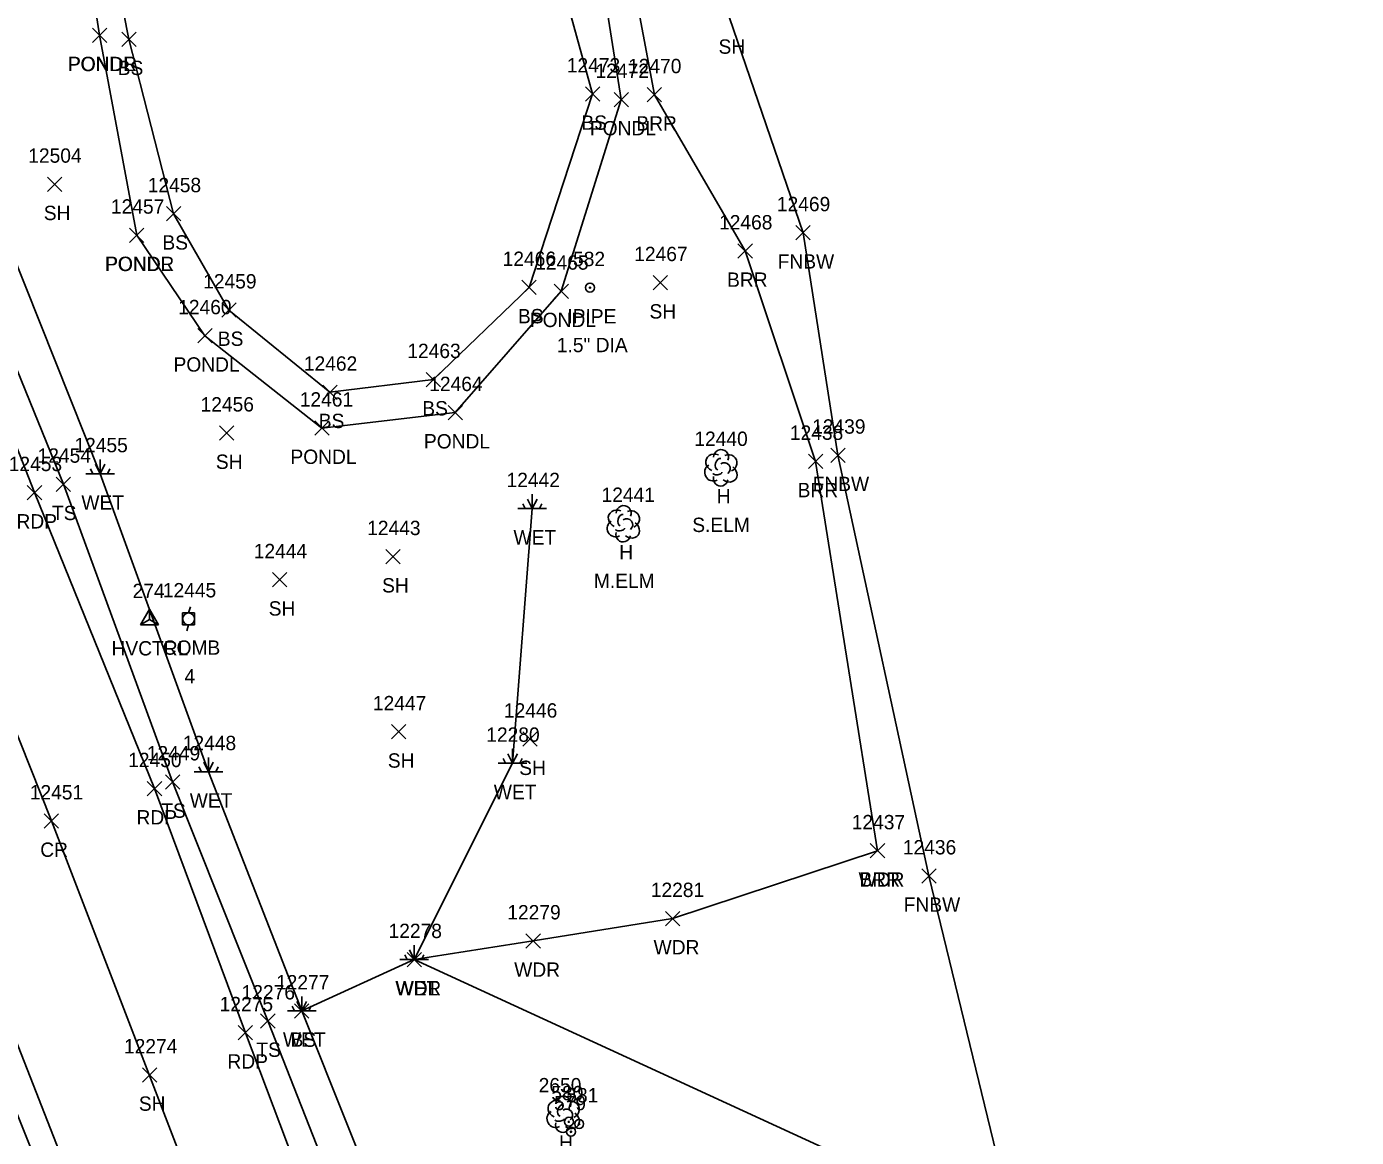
# Model space of a CAD drawing. Extents: x 1439173 to 1457902, y 641926 to 659889.
# Drawn here: x 1447721.4 to 1447906.7, y 649724.3 to 649879.1 of the extents above; entities that cross this region are included whole.
import ezdxf

# ---------------------------------------------------------------- set-up
doc = ezdxf.new("R2010")
doc.units = 0
for name, color, linetype in [('C_A', 7, 'Continuous'), ('C_I', 7, 'Continuous'), ('CPSM', 7, 'Continuous'), ('L_A', 7, 'Continuous'), ('L_C', 7, 'Continuous'), ('L_I', 7, 'Continuous'), ('L_TIC', 7, 'Continuous'), ('LABL', 7, 'Continuous'), ('LAWA', 7, 'Continuous'), ('LAWE', 7, 'Continuous'), ('LELB', 7, 'Continuous'), ('LFNC', 7, 'Continuous'), ('LSOGP', 7, 'Continuous'), ('LTD', 7, 'Continuous'), ('LWET', 7, 'Continuous'), ('M_A', 7, 'Continuous'), ('M_C', 7, 'Continuous'), ('M_I', 7, 'Continuous'), ('MPIP', 7, 'Continuous'), ('P_A', 7, 'Continuous'), ('P_I', 7, 'Continuous'), ('P_TIC', 7, 'Continuous'), ('PET', 7, 'Continuous'), ('PRC', 7, 'Continuous'), ('U_A', 7, 'Continuous'), ('U_C', 7, 'Continuous'), ('U_I', 7, 'Continuous'), ('UP', 7, 'Continuous')]:
    doc.layers.add(name, color=color, linetype=linetype)

msp = doc.modelspace()

# ---------------------------------------------------------------- linework, layer by layer
at = {"layer": 'CPSM'}
for p, q in [((1447737.3, 649795.72), (1447738.55, 649797.88)), ((1447739.8, 649795.72), (1447738.55, 649797.88)), ((1447738.55, 649796.44), (1447738.55, 649797.88)), ((1447737.3, 649795.72), (1447738.55, 649796.44)), ((1447737.3, 649795.72), (1447739.8, 649795.72)), ((1447738.55, 649796.44), (1447738.55, 649796.44)), ((1447738.55, 649796.44), (1447739.8, 649795.72))]:
    msp.add_line(p, q, dxfattribs=at)
at = {"layer": 'L_TIC'}
for points in [[(1447730.57, 649876.9), (1447732.57, 649878.9)], [(1447732.57, 649876.9), (1447730.57, 649878.9)], [(1447730.57, 649876.9), (1447732.57, 649878.9)], [(1447732.57, 649876.9), (1447730.57, 649878.9)], [(1447734.66, 649876.35), (1447736.66, 649878.35)], [(1447736.66, 649876.35), (1447734.66, 649878.35)], [(1447734.66, 649876.35), (1447736.66, 649878.35)], [(1447736.66, 649876.35), (1447734.66, 649878.35)], [(1447799.27, 649868.72), (1447801.27, 649870.72)], [(1447801.27, 649868.72), (1447799.27, 649870.72)], [(1447803.27, 649867.94), (1447805.27, 649869.94)], [(1447805.27, 649867.94), (1447803.27, 649869.94)], [(1447807.88, 649868.61), (1447809.88, 649870.61)], [(1447809.88, 649868.61), (1447807.88, 649870.61)], [(1447724.31, 649856.13), (1447726.31, 649858.13)], [(1447726.31, 649856.13), (1447724.31, 649858.13)], [(1447740.88, 649852.02), (1447742.88, 649854.02)], [(1447742.88, 649852.02), (1447740.88, 649854.02)], [(1447740.88, 649852.02), (1447742.88, 649854.02)], [(1447742.88, 649852.02), (1447740.88, 649854.02)], [(1447735.75, 649849.03), (1447737.75, 649851.03)], [(1447737.75, 649849.03), (1447735.75, 649851.03)], [(1447735.75, 649849.03), (1447737.75, 649851.03)], [(1447737.75, 649849.03), (1447735.75, 649851.03)], [(1447828.59, 649849.37), (1447830.59, 649851.37)], [(1447830.59, 649849.37), (1447828.59, 649851.37)], [(1447820.53, 649846.83), (1447822.53, 649848.83)], [(1447822.53, 649846.83), (1447820.53, 649848.83)], [(1447790.43, 649841.74), (1447792.43, 649843.74)], [(1447792.43, 649841.74), (1447790.43, 649843.74)], [(1447794.91, 649841.22), (1447796.91, 649843.22)], [(1447796.91, 649841.22), (1447794.91, 649843.22)], [(1447808.71, 649842.41), (1447810.71, 649844.41)], [(1447810.71, 649842.41), (1447808.71, 649844.41)], [(1447748.61, 649838.6), (1447750.61, 649840.6)], [(1447750.61, 649838.6), (1447748.61, 649840.6)], [(1447745.26, 649835.01), (1447747.26, 649837.01)], [(1447747.26, 649835.01), (1447745.26, 649837.01)], [(1447777.1, 649828.9), (1447779.1, 649830.9)], [(1447779.1, 649828.9), (1447777.1, 649830.9)], [(1447762.68, 649827.14), (1447764.68, 649829.14)], [(1447764.68, 649827.14), (1447762.68, 649829.14)], [(1447780.14, 649824.3), (1447782.14, 649826.3)], [(1447782.14, 649824.3), (1447780.14, 649826.3)], [(1447748.29, 649821.45), (1447750.29, 649823.45)], [(1447750.29, 649821.45), (1447748.29, 649823.45)], [(1447761.55, 649822.14), (1447763.55, 649824.14)], [(1447763.55, 649822.14), (1447761.55, 649824.14)], [(1447830.35, 649817.5), (1447832.35, 649819.5)], [(1447832.35, 649817.5), (1447830.35, 649819.5)], [(1447833.46, 649818.36), (1447835.46, 649820.36)], [(1447835.46, 649818.36), (1447833.46, 649820.36)], [(1447725.53, 649814.31), (1447727.53, 649816.31)], [(1447727.53, 649814.31), (1447725.53, 649816.31)], [(1447771.45, 649804.22), (1447773.45, 649806.22)], [(1447773.45, 649804.22), (1447771.45, 649806.22)], [(1447755.66, 649801), (1447757.66, 649803)], [(1447757.66, 649801), (1447755.66, 649803)], [(1447772.25, 649779.8), (1447774.25, 649781.8)], [(1447774.25, 649779.8), (1447772.25, 649781.8)], [(1447790.57, 649778.78), (1447792.57, 649780.78)], [(1447792.57, 649778.78), (1447790.57, 649780.78)], [(1447740.76, 649772.81), (1447742.76, 649774.81)], [(1447742.76, 649772.81), (1447740.76, 649774.81)], [(1447838.97, 649763.21), (1447840.97, 649765.21)], [(1447840.97, 649763.21), (1447838.97, 649765.21)], [(1447838.97, 649763.21), (1447840.97, 649765.21)], [(1447840.97, 649763.21), (1447838.97, 649765.21)], [(1447846.14, 649759.71), (1447848.14, 649761.71)], [(1447848.14, 649759.71), (1447846.14, 649761.71)], [(1447810.41, 649753.77), (1447812.41, 649755.77)], [(1447812.41, 649753.77), (1447810.41, 649755.77)], [(1447790.99, 649750.65), (1447792.99, 649752.65)], [(1447792.99, 649750.65), (1447790.99, 649752.65)], [(1447774.43, 649748.05), (1447776.43, 649750.05)], [(1447776.43, 649748.05), (1447774.43, 649750.05)], [(1447774.43, 649748.05), (1447776.43, 649750.05)], [(1447776.43, 649748.05), (1447774.43, 649750.05)], [(1447758.75, 649740.89), (1447760.75, 649742.89)], [(1447760.75, 649740.89), (1447758.75, 649742.89)], [(1447754.02, 649739.49), (1447756.02, 649741.49)], [(1447756.02, 649739.49), (1447754.02, 649741.49)], [(1447737.57, 649731.97), (1447739.57, 649733.97)], [(1447739.57, 649731.97), (1447737.57, 649733.97)]]:
    msp.add_lwpolyline(points, dxfattribs=at)
at = {"layer": 'LABL'}
msp.add_lwpolyline([(1447839.97, 649764.21), (1447831.35, 649818.5), (1447821.53, 649847.83), (1447808.88, 649869.61), (1447802.58, 649903.3), (1447787, 649920.26), (1447770.77, 649944.53), (1447761.79, 649968.82), (1447755.13, 650001.32), (1447731.91, 649996.86), (1447719.7, 649996.24)], dxfattribs=at)
at = {"layer": 'LAWA'}
for points in [[(1447775.43, 649749.05), (1447791.99, 649751.65), (1447811.41, 649754.77), (1447839.97, 649764.21)], [(1447775.43, 649749.05), (1447846.21, 649716.48)]]:
    msp.add_lwpolyline(points, dxfattribs=at)
at = {"layer": 'LAWE'}
for points in [[(1447736.75, 649850.03), (1447746.26, 649836.01), (1447762.55, 649823.14), (1447781.14, 649825.3), (1447795.91, 649842.22), (1447804.27, 649868.94), (1447798.96, 649902.6), (1447784.97, 649913.87), (1447757.99, 649915.79), (1447736.66, 649904.86), (1447728.59, 649897.4), (1447731.57, 649877.9)], [(1447736.75, 649850.03), (1447731.57, 649877.9)]]:
    msp.add_lwpolyline(points, dxfattribs=at)
at = {"layer": 'LELB'}
for points in [[(1447774.29, 649691.46), (1447755.02, 649740.49), (1447741.76, 649773.81), (1447726.53, 649815.31), (1447711.79, 649851.58), (1447694.8, 649894.93), (1447679.35, 649935.48), (1447671.24, 649953.99), (1447664.82, 649972.77), (1447658.14, 649990.48), (1447642.81, 650028.26), (1447624.72, 650071.67), (1447610.83, 650104.7), (1447593.41, 650149.12), (1447575.75, 650192.36), (1447557, 650239.72), (1447541.41, 650280.13), (1447523.46, 650325.06), (1447503.16, 650377.6)], [(1447723.82, 649718.23), (1447707.42, 649759.24), (1447691.24, 649802.92), (1447677.6, 649836.74), (1447660.97, 649879.47), (1447648.74, 649908.2), (1447635.58, 649941.11), (1447623.44, 649965.2), (1447610.18, 649980.39), (1447590.88, 649987.45), (1447563.69, 649981.71), (1447542.89, 649971.32), (1447515.03, 649972), (1447498.96, 649966.2), (1447485.41, 649965.68), (1447480.38, 649958.04), (1447479.78, 649949.45)], [(1447741.88, 649853.02), (1447749.61, 649839.6), (1447763.68, 649828.14), (1447778.1, 649829.9), (1447791.43, 649842.74), (1447800.27, 649869.72), (1447793.36, 649894.88), (1447781.05, 649907.1), (1447758.48, 649907.27), (1447740.49, 649898.87), (1447732.63, 649892.69), (1447735.66, 649877.35)], [(1447741.88, 649853.02), (1447735.66, 649877.35)], [(1447880.13, 649239.76), (1447875.85, 649278.11), (1447869.91, 649316.47), (1447864.43, 649354.84), (1447857.47, 649403.89), (1447849.64, 649447.67), (1447838.99, 649494.14), (1447825.85, 649553.36), (1447811.08, 649599.11), (1447797.18, 649651.08), (1447779.23, 649693.18), (1447759.75, 649741.89)]]:
    msp.add_lwpolyline(points, dxfattribs=at)
at = {"layer": 'LFNC'}
msp.add_lwpolyline([(1447906.7, 649498.5), (1447900.26, 649522.32), (1447891.02, 649568.93), (1447878.05, 649621.9), (1447866.97, 649668.6), (1447857.32, 649718.69), (1447847.14, 649760.71), (1447834.46, 649819.36), (1447829.59, 649850.37)], dxfattribs=at)
at = {"layer": 'LSOGP'}
msp.add_lwpolyline([(1447619.03, 650360.07), (1447637.42, 650315.88), (1447658.67, 650267.12), (1447673.57, 650226.26), (1447688.13, 650176.69), (1447711.15, 650147.55), (1447725.49, 650099.49), (1447742.44, 650053.11), (1447746.12, 650031.62), (1447770.15, 650000.07), (1447776.52, 649966.69), (1447797.12, 649942.22), (1447810.31, 649916.5), (1447819.33, 649880.31), (1447829.59, 649850.37), (1447834.46, 649819.36), (1447847.14, 649760.71), (1447857.32, 649718.69)], dxfattribs=at)
at = {"layer": 'LTD'}
for p, q in [((1447818.13, 649817.65), (1447818.13, 649817.65)), ((1447818.13, 649817.65), (1447818.13, 649817.65)), ((1447804.54, 649809.85), (1447804.54, 649809.85)), ((1447804.54, 649809.85), (1447804.54, 649809.85)), ((1447796.15, 649727.54), (1447796.15, 649727.54)), ((1447796.15, 649727.54), (1447796.15, 649727.54))]:
    msp.add_line(p, q, dxfattribs=at)
for centre in [(1447818.17, 649819.09), (1447804.59, 649811.28), (1447796.2, 649728.97)]:
    msp.add_arc(centre, 1.05, 335.5272, 180.9563, dxfattribs=at)
for centre, major_axis, ratio, start_param, end_param in [((1447817.34, 649818.32), (1.21, -0.51), 0.895232, 1.570796, 4.712389), ((1447817.92, 649818.11), (-0.208, -0.792), 0.645439, 3.141593, 6.283185), ((1447819.17, 649818.24), (-1.14, -0.48), 0.949671, 1.570796, 4.712389), ((1447817.04, 649816.94), (0.58, -1.04), 0.959034, 3.141593, 6.283185), ((1447817.67, 649816.9), (-0.625, -0.083), 0.423636, 0, 3.141593), ((1447818.63, 649817.49), (-0.5, 0.667), 0.989748, 3.141593, 6.283185), ((1447819.13, 649816.82), (-1.09, 0.79), 0.841452, 1.570796, 4.712389), ((1447818.13, 649816.15), (0.26, 1.06), 0.942809, 1.570796, 4.712389), ((1447803.75, 649810.52), (1.21, -0.51), 0.895232, 1.570796, 4.712389), ((1447805.58, 649810.43), (-1.14, -0.48), 0.949671, 1.570796, 4.712389), ((1447803.46, 649809.14), (0.58, -1.04), 0.959034, 3.141593, 6.283185), ((1447804.34, 649810.31), (-0.208, -0.792), 0.645439, 3.141593, 6.283185), ((1447805.04, 649809.68), (-0.5, 0.667), 0.989748, 3.141593, 6.283185), ((1447805.54, 649809.02), (-1.09, 0.79), 0.841452, 1.570796, 4.712389), ((1447804.54, 649808.35), (0.26, 1.06), 0.942809, 1.570796, 4.712389), ((1447804.09, 649809.1), (-0.625, -0.083), 0.423636, 0, 3.141593), ((1447795.36, 649728.21), (1.21, -0.51), 0.895232, 1.570796, 4.712389), ((1447795.95, 649728), (-0.208, -0.792), 0.645439, 3.141593, 6.283185), ((1447796.65, 649727.37), (-0.5, 0.667), 0.989748, 3.141593, 6.283185), ((1447797.2, 649728.12), (-1.14, -0.48), 0.949671, 1.570796, 4.712389), ((1447795.07, 649726.83), (0.58, -1.04), 0.959034, 3.141593, 6.283185), ((1447796.15, 649726.04), (0.26, 1.06), 0.942809, 1.570796, 4.712389), ((1447795.7, 649726.79), (-0.625, -0.083), 0.423636, 0, 3.141593), ((1447797.15, 649726.71), (-1.09, 0.79), 0.841452, 1.570796, 4.712389)]:
    msp.add_ellipse(centre, major_axis=major_axis, ratio=ratio, start_param=start_param, end_param=end_param, dxfattribs=at)
at = {"layer": 'LWET'}
for p, q in [((1447730.66, 649816.77), (1447730.33, 649817.44)), ((1447731.66, 649816.77), (1447730.99, 649818.11)), ((1447731.66, 649816.77), (1447731.66, 649818.77)), ((1447731.66, 649816.77), (1447732.33, 649818.11)), ((1447732.66, 649816.77), (1447732.99, 649817.44)), ((1447733.66, 649816.77), (1447729.66, 649816.77)), ((1447791.87, 649811.91), (1447791.2, 649813.24)), ((1447791.87, 649811.91), (1447791.87, 649813.91)), ((1447791.87, 649811.91), (1447792.54, 649813.24)), ((1447793.87, 649811.91), (1447789.87, 649811.91)), ((1447790.87, 649811.91), (1447790.54, 649812.57)), ((1447792.87, 649811.91), (1447793.2, 649812.57)), ((1447789.13, 649776.41), (1447789.13, 649778.41)), ((1447746.76, 649775.24), (1447746.09, 649776.57)), ((1447746.76, 649775.24), (1447746.76, 649777.24)), ((1447746.76, 649775.24), (1447747.42, 649776.57)), ((1447791.13, 649776.41), (1447787.13, 649776.41)), ((1447788.13, 649776.41), (1447787.8, 649777.08)), ((1447789.13, 649776.41), (1447788.47, 649777.75)), ((1447789.13, 649776.41), (1447789.8, 649777.75)), ((1447790.13, 649776.41), (1447790.47, 649777.08)), ((1447748.76, 649775.24), (1447744.76, 649775.24)), ((1447745.76, 649775.24), (1447745.42, 649775.9)), ((1447747.76, 649775.24), (1447748.09, 649775.9)), ((1447775.43, 649749.05), (1447774.76, 649750.39)), ((1447775.43, 649749.05), (1447775.43, 649751.05)), ((1447775.43, 649749.05), (1447776.1, 649750.39)), ((1447777.43, 649749.05), (1447773.43, 649749.05)), ((1447774.43, 649749.05), (1447774.1, 649749.72)), ((1447776.43, 649749.05), (1447776.76, 649749.72)), ((1447759.75, 649741.89), (1447759.08, 649743.22)), ((1447759.75, 649741.89), (1447759.08, 649743.22)), ((1447759.75, 649741.89), (1447759.75, 649743.89)), ((1447759.75, 649741.89), (1447759.75, 649743.89)), ((1447759.75, 649741.89), (1447760.42, 649743.22)), ((1447759.75, 649741.89), (1447760.42, 649743.22)), ((1447761.75, 649741.89), (1447757.75, 649741.89)), ((1447761.75, 649741.89), (1447757.75, 649741.89)), ((1447758.75, 649741.89), (1447758.42, 649742.56)), ((1447758.75, 649741.89), (1447758.42, 649742.56)), ((1447760.75, 649741.89), (1447761.08, 649742.56)), ((1447760.75, 649741.89), (1447761.08, 649742.56))]:
    msp.add_line(p, q, dxfattribs=at)
for points in [[(1447759.75, 649741.89), (1447746.76, 649775.24), (1447731.66, 649816.77), (1447716.96, 649853.54), (1447699.99, 649897.87), (1447692.42, 649923.04), (1447688.9, 649933.67)], [(1447759.75, 649741.89), (1447775.43, 649749.05), (1447789.13, 649776.41), (1447791.87, 649811.91)]]:
    msp.add_lwpolyline(points, dxfattribs=at)
at = {"layer": 'MPIP'}
for centre, radius in [((1447799.91, 649842.72), 0.625), ((1447799.91, 649842.72), 0.0833), ((1447796.97, 649726.44), 0.625), ((1447796.97, 649726.44), 0.0833), ((1447798.4, 649726.14), 0.625), ((1447798.4, 649726.14), 0.0833), ((1447797.27, 649725.05), 0.625), ((1447797.27, 649725.05), 0.0833)]:
    msp.add_circle(centre, radius, dxfattribs=at)
at = {"layer": 'P_TIC'}
for points in [[(1447721.51, 649813.14), (1447723.51, 649815.14)], [(1447723.51, 649813.14), (1447721.51, 649815.14)], [(1447738.23, 649771.88), (1447740.23, 649773.88)], [(1447740.23, 649771.88), (1447738.23, 649773.88)], [(1447723.87, 649767.37), (1447725.87, 649769.37)], [(1447725.87, 649767.37), (1447723.87, 649769.37)], [(1447750.9, 649737.85), (1447752.9, 649739.85)], [(1447752.9, 649737.85), (1447750.9, 649739.85)]]:
    msp.add_lwpolyline(points, dxfattribs=at)
at = {"layer": 'PET'}
for points in [[(1447770.26, 649690.21), (1447751.9, 649738.85), (1447739.23, 649772.88), (1447722.51, 649814.14), (1447708.42, 649850.04), (1447690.94, 649894.41), (1447668.44, 649951.98), (1447651.8, 649993.39), (1447639.52, 650024.92), (1447621.07, 650070.34), (1447607.4, 650104.2), (1447589.96, 650148.16), (1447572.98, 650191.37), (1447554, 650238.81), (1447538.2, 650279.02), (1447520.31, 650323.9), (1447499.97, 650376.7)], [(1447727.24, 649719.06), (1447711.09, 649760.24), (1447693.62, 649804.98), (1447680.5, 649838.27), (1447663.74, 649880.79), (1447652.33, 649909.76), (1447638.93, 649943.34), (1447628.9, 649967.78), (1447622.17, 649981.56), (1447611.58, 650013.54), (1447596.45, 650049.26), (1447579.87, 650091.8), (1447553.03, 650160.19), (1447534.14, 650208.59), (1447519.57, 650245.32), (1447501.85, 650290.55), (1447485.96, 650331.56), (1447471.86, 650366.58)]]:
    msp.add_lwpolyline(points, dxfattribs=at)
at = {"layer": 'PRC'}
msp.add_lwpolyline([(1447756.88, 649685.17), (1447724.87, 649768.37), (1447708.6, 649809.19), (1447694.68, 649845.27), (1447676.47, 649890.48), (1447654.25, 649946.92), (1447638.2, 649987.7), (1447625.62, 650020.15), (1447607.06, 650065.42), (1447594.17, 650098.1), (1447576.34, 650142.25), (1447558.92, 650186.5), (1447540.22, 650233.49), (1447524.32, 650273.63), (1447506.57, 650318.67), (1447486.08, 650370.95)], dxfattribs=at)
at = {"layer": 'UP'}
for p, q in [((1447743.15, 649795.71), (1447743.15, 649797.38)), ((1447743.15, 649797.38), (1447744.81, 649797.38)), ((1447744.23, 649798.21), (1447743.98, 649797.38)), ((1447743.98, 649796.54), (1447743.98, 649796.54)), ((1447744.81, 649797.38), (1447744.81, 649795.71)), ((1447744.81, 649795.71), (1447743.15, 649795.71)), ((1447743.73, 649794.88), (1447743.98, 649795.71))]:
    msp.add_line(p, q, dxfattribs=at)
msp.add_circle((1447743.98, 649796.54), 0.833, dxfattribs=at)

# ---------------------------------------------------------------- texts
at = {"layer": 'C_A'}
msp.add_text('HVCTRL', height=2, dxfattribs=at).set_placement((1447733.24, 649791.44))
at = {"layer": 'C_I'}
msp.add_text('274', height=2, dxfattribs=at).set_placement((1447736.18, 649799.44))
at = {"layer": 'L_A'}
for s, p in [('SH', (1447817.82, 649875.32)), ('PONDR', (1447727.13, 649872.9)), ('PONDL', (1447727.19, 649872.9)), ('BS', (1447734.1, 649872.35)), ('BS', (1447734.1, 649872.35)), ('BS', (1447798.71, 649864.72)), ('PONDL', (1447799.89, 649863.94)), ('BRR', (1447806.37, 649864.61)), ('SH', (1447723.8, 649852.13)), ('BS', (1447740.33, 649848.02)), ('BS', (1447740.33, 649848.02)), ('PONDR', (1447732.32, 649845.03)), ('PONDL', (1447732.38, 649845.03)), ('FNBW', (1447826.06, 649845.37)), ('BRR', (1447819.01, 649842.83)), ('BS', (1447789.87, 649837.74)), ('PONDL', (1447791.53, 649837.22)), ('SH', (1447808.2, 649838.41)), ('BS', (1447748.05, 649834.6)), ('PONDL', (1447741.88, 649831.01)), ('BS', (1447776.54, 649824.9)), ('BS', (1447762.12, 649823.14)), ('PONDL', (1447776.77, 649820.3)), ('SH', (1447747.78, 649817.45)), ('PONDL', (1447758.17, 649818.14)), ('BRR', (1447828.84, 649813.5)), ('FNBW', (1447830.93, 649814.36)), ('WET', (1447729.04, 649811.77)), ('H', (1447817.56, 649812.65)), ('TS', (1447724.94, 649810.31)), ('WET', (1447789.25, 649806.91)), ('H', (1447803.98, 649804.85)), ('SH', (1447770.94, 649800.22)), ('SH', (1447755.14, 649797)), ('SH', (1447771.74, 649775.8)), ('SH', (1447790.05, 649774.78)), ('WET', (1447786.51, 649771.41)), ('TS', (1447740.17, 649768.81)), ('WET', (1447744.14, 649770.24)), ('WDR', (1447837.33, 649759.21)), ('BRR', (1447837.46, 649759.21)), ('FNBW', (1447843.62, 649755.71)), ('WDR', (1447808.77, 649749.77)), ('WDR', (1447789.35, 649746.65)), ('WDR', (1447772.79, 649744.05)), ('WET', (1447772.81, 649744.05)), ('WDL', (1447772.85, 649744.05)), ('TS', (1447753.42, 649735.49)), ('WET', (1447757.13, 649736.89)), ('WET', (1447757.13, 649736.89)), ('BS', (1447758.19, 649736.89)), ('SH', (1447737.05, 649727.97)), ('H', (1447795.59, 649722.54))]:
    msp.add_text(s, height=2, dxfattribs=at).set_placement(p)
at = {"layer": 'L_C'}
for s, p in [('S.ELM', (1447814.16, 649808.65)), ('M.ELM', (1447800.45, 649800.85))]:
    msp.add_text(s, height=2, dxfattribs=at).set_placement(p)
at = {"layer": 'L_I'}
for s, p in [('12473', (1447796.68, 649872.72)), ('12470', (1447805.21, 649872.61)), ('12472', (1447800.68, 649871.94)), ('12504', (1447721.64, 649860.13)), ('12458', (1447738.29, 649856.02)), ('12458', (1447738.29, 649856.02)), ('12457', (1447733.16, 649853.03)), ('12457', (1447733.16, 649853.03)), ('12469', (1447825.95, 649853.37)), ('12468', (1447817.89, 649850.83)), ('12467', (1447806.07, 649846.41)), ('12466', (1447787.74, 649845.74)), ('12465', (1447792.27, 649845.22)), ('12459', (1447746.01, 649842.6)), ('12460', (1447742.53, 649839.01)), ('12463', (1447774.46, 649832.9)), ('12462', (1447760.04, 649831.14)), ('12464', (1447777.51, 649828.3)), ('12461', (1447759.47, 649826.14)), ('12456', (1447745.65, 649825.45)), ('12439', (1447830.86, 649822.36)), ('12440', (1447814.45, 649820.65)), ('12438', (1447827.76, 649821.5)), ('12455', (1447728.07, 649819.77)), ('12454', (1447722.94, 649818.31)), ('12442', (1447788.28, 649814.91)), ('12441', (1447801.52, 649812.85)), ('12443', (1447768.86, 649808.22)), ('12444', (1447753.06, 649805)), ('12447', (1447769.66, 649783.8)), ('12446', (1447787.92, 649782.78)), ('12448', (1447743.17, 649778.24)), ('12280', (1447785.46, 649779.41)), ('12449', (1447738.16, 649776.81)), ('12437', (1447836.38, 649767.21)), ('12437', (1447836.38, 649767.21)), ('12436', (1447843.5, 649763.71)), ('12281', (1447808.38, 649757.77)), ('12279', (1447788.39, 649754.65)), ('12278', (1447771.84, 649752.05)), ('12278', (1447771.84, 649752.05)), ('12278', (1447771.84, 649752.05)), ('12277', (1447756.16, 649744.89)), ('12277', (1447756.16, 649744.89)), ('12277', (1447756.16, 649744.89)), ('12276', (1447751.37, 649743.49)), ('12274', (1447734.98, 649735.97)), ('2650', (1447792.76, 649730.54))]:
    msp.add_text(s, height=2, dxfattribs=at).set_placement(p)
at = {"layer": 'M_A'}
msp.add_text('IPIPE', height=2, dxfattribs=at).set_placement((1447796.75, 649837.72))
at = {"layer": 'M_C'}
msp.add_text('1.5" DIA', height=2, dxfattribs=at).set_placement((1447795.29, 649833.72))
at = {"layer": 'M_I'}
for s, p in [('582', (1447797.55, 649845.72)), ('580', (1447794.52, 649729.44)), ('579', (1447794.9, 649728.05)), ('581', (1447796.61, 649729.14))]:
    msp.add_text(s, height=2, dxfattribs=at).set_placement(p)
at = {"layer": 'P_A'}
for s, p in [('RDP', (1447720, 649809.14)), ('RDP', (1447736.72, 649767.88)), ('CR', (1447723.31, 649763.37)), ('RDP', (1447749.39, 649733.85))]:
    msp.add_text(s, height=2, dxfattribs=at).set_placement(p)
at = {"layer": 'P_I'}
for s, p in [('12453', (1447718.92, 649817.14)), ('12450', (1447735.56, 649775.88)), ('12451', (1447721.85, 649771.37)), ('12275', (1447748.31, 649741.85))]:
    msp.add_text(s, height=2, dxfattribs=at).set_placement(p)
at = {"layer": 'U_A'}
msp.add_text('COMB', height=2, dxfattribs=at).set_placement((1447740.37, 649791.54))
at = {"layer": 'U_C'}
msp.add_text('4', height=2, dxfattribs=at).set_placement((1447743.41, 649787.54))
at = {"layer": 'U_I'}
msp.add_text('12445', height=2, dxfattribs=at).set_placement((1447740.39, 649799.54))

doc.saveas('drawing.dxf')
